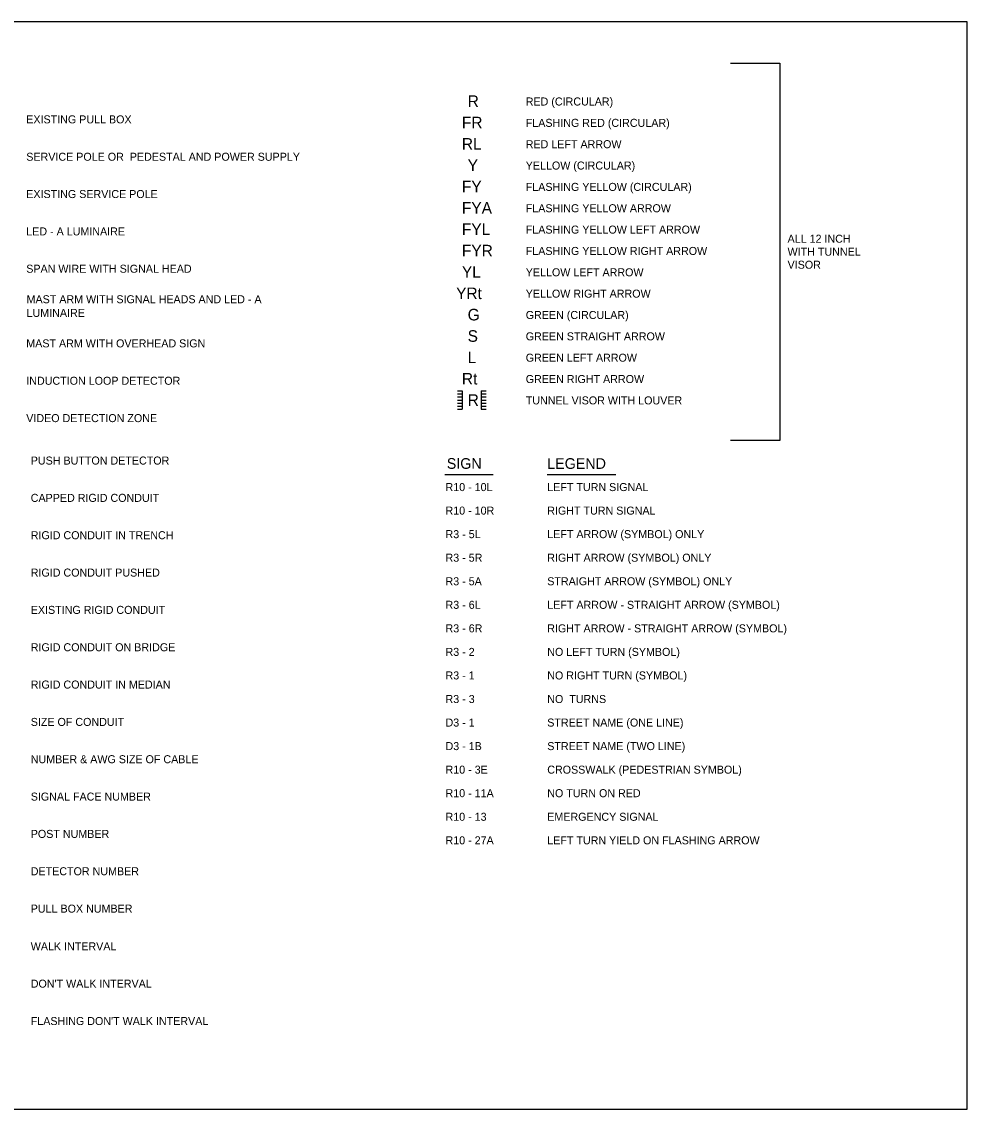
# Model space of a CAD drawing. Extents: x -439.1 to -407.9, y -458.1 to -437.7.
# Drawn here: x -425.57 to -407.86, y -458.05 to -437.68 of the extents above; entities that cross this region are included whole.
import ezdxf

# ---------------------------------------------------------------- set-up
doc = ezdxf.new("R2010")
doc.units = 0
doc.layers.add('Draft_Named_Boundary', color=7, linetype='Continuous')
doc.layers.add('Level 4', color=7, linetype='Continuous')

msp = doc.modelspace()

# ---------------------------------------------------------------- linework, layer by layer
at = {"layer": 'Draft_Named_Boundary'}
msp.add_lwpolyline([(-439.109, -458.051), (-407.859, -458.051), (-407.859, -437.676), (-439.109, -437.676)], close=True, dxfattribs=at)
at = {"layer": 'Level 4'}
for p, q in [((-412.293, -438.45), (-411.371, -438.45)), ((-411.371, -438.45), (-411.371, -445.523)), ((-417.408, -444.592), (-417.319, -444.592)), ((-417.408, -444.649), (-417.319, -444.649)), ((-417.408, -444.706), (-417.319, -444.706)), ((-417.408, -444.764), (-417.319, -444.764)), ((-417.319, -444.592), (-417.319, -444.935)), ((-416.962, -444.592), (-416.962, -444.935)), ((-416.962, -444.592), (-416.873, -444.592)), ((-416.962, -444.649), (-416.873, -444.649)), ((-416.962, -444.706), (-416.873, -444.706)), ((-416.962, -444.764), (-416.873, -444.764)), ((-417.408, -444.821), (-417.319, -444.821)), ((-417.408, -444.878), (-417.319, -444.878)), ((-417.408, -444.935), (-417.319, -444.935)), ((-416.962, -444.821), (-416.873, -444.821)), ((-416.962, -444.878), (-416.873, -444.878)), ((-416.962, -444.935), (-416.873, -444.935)), ((-411.371, -445.523), (-412.293, -445.523)), ((-417.646, -446.157), (-416.741, -446.157)), ((-415.73, -446.157), (-414.445, -446.157))]:
    msp.add_line(p, q, dxfattribs=at)

# ---------------------------------------------------------------- texts
for s, height, p in [('R', 0.217, (-417.218, -439.272)), ('RED (CIRCULAR)', 0.15, (-416.13, -439.245)), ('EXISTING PULL BOX', 0.15, (-425.487, -439.58)), ('FR', 0.2167, (-417.326, -439.672)), ('FLASHING RED (CIRCULAR)', 0.15, (-416.13, -439.645)), ('RL', 0.2167, (-417.326, -440.072)), ('RED LEFT ARROW', 0.15, (-416.13, -440.045)), ('SERVICE POLE OR  PEDESTAL AND POWER SUPPLY', 0.15, (-425.487, -440.28)), ('Y', 0.217, (-417.218, -440.472)), ('YELLOW (CIRCULAR)', 0.15, (-416.13, -440.445)), ('FY', 0.2167, (-417.326, -440.872)), ('FY', 0.2167, (-417.326, -440.872)), ('FY', 0.2167, (-417.326, -440.872)), ('FLASHING YELLOW (CIRCULAR)', 0.15, (-416.13, -440.845)), ('EXISTING SERVICE POLE', 0.15, (-425.487, -440.979)), ('FY', 0.2167, (-417.326, -441.272)), ('FY', 0.2167, (-417.326, -441.272)), ('FYA', 0.2167, (-417.326, -441.272)), ('FLASHING YELLOW ARROW', 0.15, (-416.13, -441.245)), ('FYL', 0.2167, (-417.326, -441.672)), ('FLASHING YELLOW LEFT ARROW', 0.15, (-416.13, -441.645)), ('LED - A LUMINAIRE', 0.15, (-425.487, -441.679)), ('ALL 12 INCH', 0.15, (-411.225, -441.816)), ('FYR', 0.2167, (-417.326, -442.072)), ('FLASHING YELLOW RIGHT ARROW', 0.15, (-416.13, -442.045)), ('WITH TUNNEL', 0.15, (-411.225, -442.059)), ('SPAN WIRE WITH SIGNAL HEAD', 0.15, (-425.487, -442.378)), ('YL', 0.2167, (-417.326, -442.472)), ('YELLOW LEFT ARROW', 0.15, (-416.13, -442.445)), ('VISOR', 0.15, (-411.225, -442.303)), ('YRt', 0.2167, (-417.434, -442.872)), ('YELLOW RIGHT ARROW', 0.15, (-416.13, -442.845)), ('MAST ARM WITH SIGNAL HEADS AND LED - A', 0.15, (-425.481, -442.95)), ('LUMINAIRE', 0.15, (-425.481, -443.206)), ('G', 0.217, (-417.218, -443.272)), ('GREEN (CIRCULAR)', 0.15, (-416.13, -443.245)), ('S', 0.217, (-417.218, -443.672)), ('GREEN STRAIGHT ARROW', 0.15, (-416.13, -443.645)), ('MAST ARM WITH OVERHEAD SIGN', 0.15, (-425.487, -443.777)), ('L', 0.217, (-417.218, -444.072)), ('GREEN LEFT ARROW', 0.15, (-416.13, -444.045)), ('INDUCTION LOOP DETECTOR', 0.15, (-425.487, -444.477)), ('Rt', 0.2167, (-417.326, -444.472)), ('GREEN RIGHT ARROW', 0.15, (-416.13, -444.445)), ('R', 0.217, (-417.218, -444.872)), ('TUNNEL VISOR WITH LOUVER', 0.15, (-416.13, -444.845)), ('VIDEO DETECTION ZONE', 0.15, (-425.487, -445.177)), ('PUSH BUTTON DETECTOR', 0.15, (-425.403, -445.972)), ('SIGN ', 0.2, (-417.609, -446.052)), ('LEGEND   ', 0.2, (-415.727, -446.053)), ('R10 - 10L', 0.15, (-417.633, -446.469)), ('LEFT TURN SIGNAL', 0.15, (-415.727, -446.469)), ('CAPPED RIGID CONDUIT', 0.15, (-425.403, -446.671)), ('R10 - 10R', 0.15, (-417.633, -446.91)), ('RIGHT TURN SIGNAL', 0.15, (-415.727, -446.91)), ('RIGID CONDUIT IN TRENCH', 0.15, (-425.403, -447.371)), ('R3 - 5L', 0.15, (-417.633, -447.351)), ('LEFT ARROW (SYMBOL) ONLY', 0.15, (-415.727, -447.351)), ('RIGHT ARROW (SYMBOL) ONLY', 0.15, (-415.727, -447.792)), ('R3 - 5R', 0.15, (-417.633, -447.792)), ('RIGID CONDUIT PUSHED', 0.15, (-425.403, -448.071)), ('R3 - 5A', 0.15, (-417.633, -448.234)), ('STRAIGHT ARROW (SYMBOL) ONLY', 0.15, (-415.727, -448.234)), ('EXISTING RIGID CONDUIT', 0.15, (-425.403, -448.77)), ('R3 - 6L', 0.15, (-417.633, -448.675)), ('LEFT ARROW - STRAIGHT ARROW (SYMBOL)', 0.15, (-415.727, -448.675)), ('R3 - 6R', 0.15, (-417.633, -449.116)), ('RIGHT ARROW - STRAIGHT ARROW (SYMBOL)', 0.15, (-415.727, -449.116)), ('RIGID CONDUIT ON BRIDGE', 0.15, (-425.403, -449.47)), ('R3 - 2', 0.15, (-417.633, -449.557)), ('NO LEFT TURN (SYMBOL)', 0.15, (-415.727, -449.557)), ('R3 - 1', 0.15, (-417.633, -449.998)), ('NO RIGHT TURN (SYMBOL)', 0.15, (-415.727, -449.998)), ('RIGID CONDUIT IN MEDIAN', 0.15, (-425.403, -450.169)), ('R3 - 3', 0.15, (-417.633, -450.44)), ('NO  TURNS', 0.15, (-415.727, -450.44)), ('SIZE OF CONDUIT', 0.15, (-425.403, -450.869)), ('D3 - 1', 0.15, (-417.633, -450.881)), ('STREET NAME (ONE LINE)', 0.15, (-415.727, -450.881)), ('D3 - 1B', 0.15, (-417.633, -451.322)), ('STREET NAME (TWO LINE)', 0.15, (-415.727, -451.322)), ('NUMBER & AWG SIZE OF CABLE', 0.15, (-425.403, -451.568)), ('R10 - 3E', 0.15, (-417.633, -451.763)), ('CROSSWALK (PEDESTRIAN SYMBOL)', 0.15, (-415.727, -451.763)), ('SIGNAL FACE NUMBER', 0.15, (-425.403, -452.268)), ('R10 - 11A', 0.15, (-417.633, -452.204)), ('NO TURN ON RED', 0.15, (-415.727, -452.204)), ('R10 - 13', 0.15, (-417.633, -452.646)), ('EMERGENCY SIGNAL', 0.15, (-415.727, -452.646)), ('POST NUMBER', 0.15, (-425.403, -452.967)), ('R10 - 27A', 0.15, (-417.633, -453.087)), ('LEFT TURN YIELD ON FLASHING ARROW', 0.15, (-415.727, -453.087)), ('DETECTOR NUMBER', 0.15, (-425.403, -453.667)), ('PULL BOX NUMBER', 0.15, (-425.403, -454.367)), ('WALK INTERVAL', 0.15, (-425.403, -455.074)), ("DON'T WALK INTERVAL", 0.15, (-425.403, -455.773)), ("FLASHING DON'T WALK INTERVAL", 0.15, (-425.403, -456.473))]:
    msp.add_text(s, height=height, dxfattribs=at).set_placement(p)

doc.saveas('drawing.dxf')
